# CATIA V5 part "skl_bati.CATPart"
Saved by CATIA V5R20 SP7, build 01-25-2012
Part number: skl_bati
Publications: "Axe pivot Bati/AB", "Axe pivot Bati/EF", "Axe pivot Bati/DC", "Plan Bati"
Bounding box of the stored display mesh (mm): x 0 to 0, y -20 to 60, z 0 to 10
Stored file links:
  U:\IAO_bon\skl_bati.CATPart
  U:\IAO_bon\skl_IAO.CATProduct
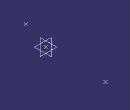
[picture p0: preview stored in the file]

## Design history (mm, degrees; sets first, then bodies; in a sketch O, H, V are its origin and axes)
Set1
  Plane1 "Plan Ref": linked copy from another document
  Point1 "Point A": linked copy from another document
  Point2 "Point E": linked copy from another document
  Point3 "Point D": linked copy from another document
Set2
  Line1 "Axe pivot Bati/AB": type Normal, RefPoint Point1, RefSkin Plane1, Start 0, End 20
  Line2 "Axe pivot Bati/EF": type Normal, RefPoint Point2, RefSkin Plane1, Start 0, End 20
  Line3 "Axe pivot Bati/DC": type Normal, RefPoint Point3, RefSkin Plane1, Start 0, End 20
  Plane2 "Plan Bati": type Normal, Curve Line2, RefPoint Point2
Body1 (main body)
